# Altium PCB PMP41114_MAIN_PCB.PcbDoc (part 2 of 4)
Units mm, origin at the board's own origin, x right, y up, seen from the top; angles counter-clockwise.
Board outline 159.1 x 70 mm, 6 copper layers (Top Layer, Signal Layer 1, Signal Layer 2, Signal Layer 3, Signal Layer 4, Bottom Layer), stack 1.671 mm thick; 188 components, 146 nets, 720 pads, 326 vias.
Unrouted connection lines stored in the file: 209.
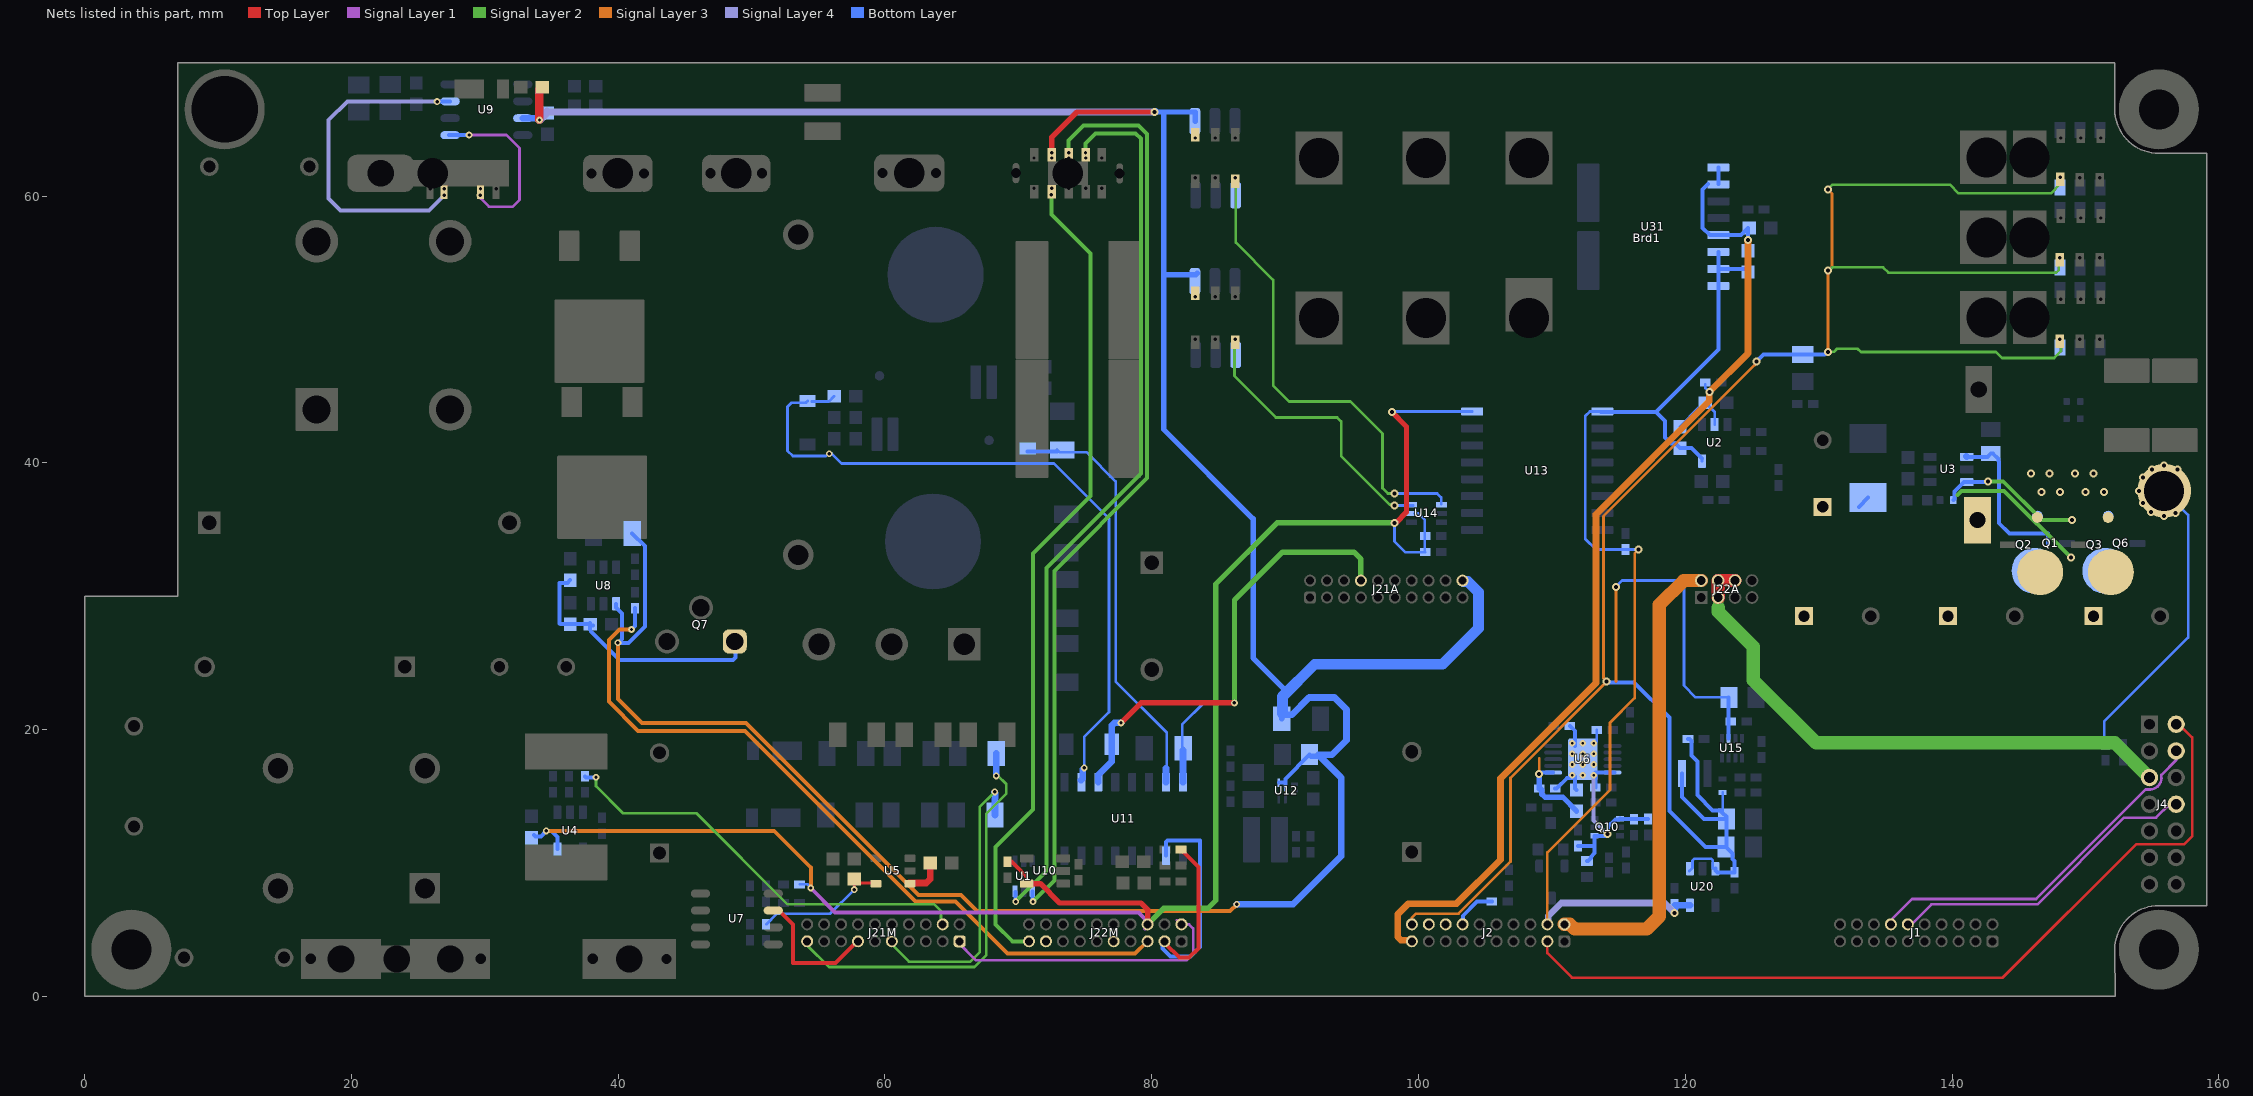
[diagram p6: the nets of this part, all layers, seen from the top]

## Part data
Brd1: library part PMP41114_LLC_MODULE, "3.6kW 400V to 54V FB LLC Module"
C1 C8 C10 C21: library part CMP-0007404-4, "CAP, CERM, 0.1 uF, 25 V, +/- 10%, X7R, 0603", Cap_Case=0603, Manufacturer=MuRata, Supplier Part Number 1=490-1524-1-ND, TempCo=X7R, Tolerance_%=10%, Value1=Unknown, Value2=25V, ValueDisplayed=0.1uF
C2 C3: library part CMP-0091050-1, "TDK 1µF Multilayer Ceramic Capacitor MLCC 500V dc ±20% SMD", Digikey Part Number=495-75234-1-ND, Manufacturer=TDK, Mouser Part Number=871-B58031U5105M062, Operating Temperature Range="-40°C to +150°C", Tolerance_%=20%, ValueDisplayed=1uF
C4 C4A C5 C6: library part CMP-0009877-2, "CAP, AL, 330 uF, 63 V, +/- 20%, 0.045 ohm, TH", Cap_Case=10x25mm, Manufacturer=Chemi-Con, Supplier Part Number 1=565-3965-ND, Tolerance_%=20%, Value1="0.045 ohm", Value2=63V, ValueDisplayed=330uF
C7 C13: library part CMP-0007197-4, "CAP, CERM, 220 pF, 50 V, +/- 5%, C0G/NP0, 0603", Cap_Case=0603, Manufacturer=MuRata, Supplier Part Number 1=490-1435-1-ND, TempCo=C0G/NP0, Tolerance_%=5%, Value1=Unknown, Value2=50V, ValueDisplayed=220pF
C9: library part CMP-0006663-2, "CAP, CERM, 2200 pF, 25 V, +/- 10%, X7R, 0402", Cap_Case=0402, Manufacturer=MuRata, Supplier Part Number 1=490-5419-1-ND, TempCo=X7R, Tolerance_%=10%, Value1=Unknown, Value2=25V, ValueDisplayed=2200pF
C11 C34 C35 C36: library part CMP-0008305-2, "CAP, CERM, 22 uF, 25 V, +/- 20%, X5R, 0805", Cap_Case=0805, Manufacturer=MuRata, Supplier Part Number 1=490-10749-1-ND, TempCo=X5R, Tolerance_%=20%, Value1=Unknown, Value2=25V, ValueDisplayed=22uF
C14: library part CMP-0097294-1, "0.1 µF ±10% 100V Ceramic Capacitor X7R 0603 (1608 Metric)", Digikey Part Number=732-885012206120TR-ND, Manufacturer="Wurth Electronics", Mouser Part Number=710-885012206120, Operating Temperature Range="-55°C to +125°C", TempCo=15%, Temperature Characteristic=X7R, Tolerance_%=10%, ValueDisplayed=100nF
C15 C16 C22: library part CMP-0006563-2, "CAP, CERM, 1 uF, 10 V, +/- 10%, X5R, 0402", Cap_Case=0402, Manufacturer=MuRata, Supplier Part Number 1=490-3890-1-ND, TempCo=X5R, Tolerance_%=10%, Value1=Unknown, Value2=10V, ValueDisplayed=1uF
C17: library part CMP-0007499-4, "CAP, CERM, 2.2 uF, 16 V, +/- 10%, X7R, 0603", Cap_Case=0603, Manufacturer=MuRata, Supplier Part Number 1=81-GRM188Z71C225KE3D, TempCo=X7R, Tolerance_%=10%, Value1=Unknown, Value2=16V, ValueDisplayed=2.2uF
C18: library part CMP-0006641-2, "CAP, CERM, 0.1 uF, 16 V, +/- 10%, X7R, 0402", Cap_Case=0402, Manufacturer=MuRata, Supplier Part Number 1=490-3261-1-ND, TempCo=X7R, Tolerance_%=10%, Value1=Unknown, Value2=16V, ValueDisplayed=0.1uF
C19 C58 C68 C69: library part CMP-0006200-2, "CAP, CERM, 100 pF, 16 V, +/- 10%, X7R, 0402", Cap_Case=0402, Manufacturer=AVX, Supplier Part Number 1=478-7887-1-ND, TempCo=X7R, Tolerance_%=10%, Value1=Unknown, Value2=16V, ValueDisplayed=100pF
C20: library part CMP-0861070-2, "CAP, CERM, 1 µF, 100 V,+/- 10%, X7R, AEC-Q200 Grade 1, 0805", Cap_Case=0805, Manufacturer=AVX, TempCo=X7R, Tolerance_%=10%, Value2=100V, ValueDisplayed=1µF
C23 C27 C28: library part CMP-0006691-2, "CAP, CERM, 470 pF, 50 V, +/- 10%, X7R, 0402", Cap_Case=0402, Manufacturer=MuRata, Supplier Part Number 1=490-1300-1-ND, TempCo=X7R, Tolerance_%=10%, Value1=Unknown, Value2=50V, ValueDisplayed=470pF
C24: library part CMP-0006225-2, "CAP, CERM, 2200 pF, 16 V, +/- 10%, X7R, 0402", Cap_Case=0402, Manufacturer="Wurth Elektronik", TempCo=X7R, Tolerance_%=10%, Value1=Unknown, Value2=16V, ValueDisplayed=2200pF
C25: library part CMP-0120172-1, "10000 pF ±5% 50V Ceramic Capacitor X7R 0603 (1608 Metric)", Digikey Part Number=399-C0603C103J5RAC7867CT-ND, Manufacturer=KEMET, Mouser Part Number=80-C0603C103J5R, Operating Temperature Range="-55°C to +125°C", TempCo=15%, Temperature Characteristic=X7R, Tolerance_%=5%, ValueDisplayed=0.01uF
C26: library part CMP-0080632-1, "CAP, CERM, 1 µF, 10 V,+/- 10%, X7R, 0603", Cap_Case=0603, Manufacturer="Taiyo Yuden", Supplier Part Number 1=587-1242-1-ND, TempCo=X7R, Tolerance_%=10%, Value2=10V, ValueDisplayed=1µF
C29 C30: library part CMP-0006659-2, "CAP, CERM, 0.1 uF, 25 V, +/- 10%, X7R, 0402", Cap_Case=0402, Manufacturer=MuRata, Supplier Part Number 1=490-10698-1-ND, TempCo=X7R, Tolerance_%=10%, Value1=Unknown, Value2=25V, ValueDisplayed=0.1uF
C31 C32 C33 C39 C40: library part CMP-0006752-5, "CAP, CERM, 0.1 uF, 25 V, +/- 5%, X7R, 0603", Cap_Case=0603, Manufacturer=AVX, Supplier Part Number 1=478-3713-1-ND, TempCo=X7R, Tolerance_%=5%, Value1="0.05 ohm", Value2=25V, ValueDisplayed=0.1uF
C41 C42 C48: library part CMP-0009613-2, "CAP, CERM, 2200 pF, 300 V, +/- 20%, E, TH, 2- Leads, Body 9x7mm, Pin Spacing 7.5mm", Cap_Case=9x7x9mm, Manufacturer=MuRata, Supplier Part Number 1=DE6E3KJ222MN3A-ND, TempCo=E, Tolerance_%=20%, Value1=Unknown, Value2=300V, ValueDisplayed=2200pF
C44: library part CMP-0090549-1, "0.47µF Film Capacitor 310V 630V Polypropylene (PP), Metallized Radial", Digikey Part Number=399-12369-ND, Manufacturer=Kemet, Mouser Part Number=80-F862BY474K310ZL, Operating Temperature Range="-40°C to +110°C", Tolerance_%=10%, ValueDisplayed=0.47uF
C45: library part CMP-0093436-1, "1.5 µF Film Capacitor 310V - Polypropylene (PP), Metallized Radial", Digikey Part Number=732-5863-ND, Manufacturer="Wurth Electronics", Mouser Part Number=710-890334026030, Operating Temperature Range="-40°C to +105°C", Tolerance_%=10%, ValueDisplayed=1.5uF
C52 C53: library part CMP-0009248-2, "CAP, CERM, 0.022 uF, 630 V, +/- 10%, X7R, 1210", Cap_Case=1210, Manufacturer=MuRata, Supplier Part Number 1=490-3514-1-ND, TempCo=X7R, Tolerance_%=10%, Value1=Unknown, Value2=630V, ValueDisplayed=0.022uF
C54: library part CMP-0064947-2, "CAP, CERM, 1 uF, 6.3 V,+/- 10%, X7R, 0402", Cap_Case=0402, Manufacturer=MuRata, Supplier Part Number 1=490-10024-1-ND, TempCo=X7R, Tolerance_%=10%, Value1=Unknown, Value2=6.3V, ValueDisplayed=1uF
C55 C62 C63 C981 C982: library part CMP-0006623-2, "CAP, CERM, 0.1 uF, 6.3 V, +/- 10%, X7R, 0402", Cap_Case=0402, Manufacturer=MuRata, Supplier Part Number 1=GRM155R70J104KA01D-ND, TempCo=X7R, Tolerance_%=10%, Value1=Unknown, Value2=6.3V, ValueDisplayed=0.1uF
C56: library part CMP-0006529-2, "CAP, CERM, 1000 pF, 6.3 V, +/- 10%, X5R, 0402", Cap_Case=0402, Manufacturer=MuRata, Supplier Part Number 1=GRM155R60J102KA01D-ND, TempCo=X5R, Tolerance_%=10%, Value1=Unknown, Value2=6.3V, ValueDisplayed=1000pF
C57 C59: library part CMP-0007678-2, "CAP, CERM, 10 uF, 16 V, +/- 20%, X5R, 0805", Cap_Case=0805, Manufacturer=AVX, Supplier Part Number 1=1582704, TempCo=X5R, Tolerance_%=20%, Value1=Unknown, Value2=16V, ValueDisplayed=10uF
C60 C74: library part CMP-0008691-2, "CAP, CERM, 1 uF, 25 V, +/- 10%, X7R, 1206", Cap_Case=1206, Manufacturer=TDK, Supplier Part Number 1=445-1592-1-ND, TempCo=X7R, Tolerance_%=10%, Value1="0.01 ohm", Value2=25V, ValueDisplayed=1uF
C61: library part CMP-0007040-4, "CAP, CERM, 1 uF, 25 V, +/- 10%, X7R, 0603", Cap_Case=0603, Manufacturer=TDK, Supplier Part Number 1=445-5956-1-ND, TempCo=X7R, Tolerance_%=10%, Value1=Unknown, Value2=25V, ValueDisplayed=1uF
C64 C65: library part CMP-0006764-4, "CAP, CERM, 1000 pF, 50 V, +/- 10%, C0G/NP0, 0603", Cap_Case=0603, Manufacturer=AVX, Supplier Part Number 1=478-3718-1-ND, TempCo=C0G/NP0, Tolerance_%=10%, Value1="0.048 ohm", Value2=50V, ValueDisplayed=1000pF
C66: library part CMP-0006978-4, "CAP, CERM, 0.01 uF, 50 V, +/- 10%, X7R, 0603", Cap_Case=0603, Manufacturer=Kemet, Supplier Part Number 1=399-5346-1-ND, TempCo=X7R, Tolerance_%=10%, Value1=Unknown, Value2=50V, ValueDisplayed=0.01uF
C67: library part CMP-0008641-2, "CAP, CERM, 0.1 uF, 25 V, +/- 5%, C0G/NP0, 1206_190", Cap_Case=1206, Manufacturer=Kemet, Supplier Part Number 1=399-5750-1-ND, TempCo=C0G/NP0, Tolerance_%=5%, Value1=Unknown, Value2=25V, ValueDisplayed=0.1uF
C70: library part CMP-0008689-2, "CAP, CERM, 10 uF, 10 V, +/- 20%, X7R, 1206", Cap_Case=1206, Manufacturer=TDK, Supplier Part Number 1=445-1602-1-ND, TempCo=X7R, Tolerance_%=20%, Value1="0.0046 ohm", Value2=10V, ValueDisplayed=10uF
C71: library part CMP-0007728-2, "CAP, CERM, 1 uF, 25 V, +/- 10%, X7R, 0805", Cap_Case=0805, Manufacturer=Kemet, Supplier Part Number 1=399-8004-1-ND, TempCo=X7R, Tolerance_%=10%, Value1=Unknown, Value2=25V, ValueDisplayed=1uF
C73: library part CMP-0007989-2, "CAP, CERM, 22 uF, 6.3 V, +/- 10%, X5R, 0805", Cap_Case=0805, Manufacturer="Samsung Electro-Mechanics", TempCo=X5R, Tolerance_%=10%, Value1=Unknown, Value2=6.3V, ValueDisplayed=22uF
C75: library part CMP-0007402-5, "CAP, CERM, 1000 pF, 25 V, +/- 10%, X7R, 0603", Cap_Case=0603, Manufacturer=MuRata, Supplier Part Number 1=GRM188R71E102KA01D-ND, TempCo=X7R, Tolerance_%=10%, Value1=Unknown, Value2=25V, ValueDisplayed=1000pF
C76: library part CMP-0006201-2, "CAP, CERM, 0.1 uF, 16 V, +/- 10%, X7R, 0402", Cap_Case=0402, Manufacturer=AVX, Supplier Part Number 1=478-7888-1-ND, TempCo=X7R, Tolerance_%=10%, Value1=Unknown, Value2=16V, ValueDisplayed=0.1uF
C114 C120 C123 C130: library part CMP-0098127-1, "180 µF 450 V Aluminum Electrolytic Capacitors Radial, Can 3000 Hrs @ 105°C", Digikey Part Number=1189-450HXW180MEFR16X50-ND, Leakage Current=853.8uA, Manufacturer=Rubycon, Mouser Part Number=232-450HXW180MEFR16X, Operating Temperature Range="-40°C to +105°C", Tolerance_%=20%, ValueDisplayed=180uF
C215: library part CMP-0006708-2, "CAP, CERM, 3300 pF, 100 V, +/- 10%, X7R, 0402", Cap_Case=0402, Manufacturer=MuRata, Supplier Part Number 1=GRM155R72A332KA01D-ND, TempCo=X7R, Tolerance_%=10%, Value1=Unknown, Value2=100V, ValueDisplayed=3300pF
D1 D2: library part CMP-0086603-1, "DIODE GEN PURPOSE 600V SLIMDPAK", Manufacturer=Vishay
D3: library part CMP-0028394-2, "Diode, Schottky, 80 V, 1 A, SMB", Manufacturer="Diodes Inc.", Value1=1A, Value2=0.79V
D4: library part CMP-0076979-3, "Diode, Switching, 100 V, 0.25 A, SOD-523", Manufacturer=Nexperia, Value1=0.25A, Value2=1.25V
D8 D10: library part CMP-0028548-2, "Diode, Schottky, 40 V, 1 A, SOD-123FL", Manufacturer="ON Semiconductor", Value1=1A, Value2=0.55V
D9 D12 D15: library part CMP-0076978-2, "Diode, Standard Recovery Rectifier, 600 V, 1 A, PowerDI123", Manufacturer="Diodes Inc.", Value1=1A, Value2=1.1V
D11: library part CMP-0090872-1, "Diode Array 1 Pair Common Cathode Standard 600V 30A Through Hole TO-3P-3, SC-65-3", Digikey Part Number=FFA60UA60DN-ND, Forward Current=30A, Manufacturer="ON Semiconductor", Max Surge Forward Current=180A, Mouser Part Number=512-FFA60UA60DN, Operating Temperature Range="-65°C to +175°C", Peak Reverse Current=100uA
J1 J2 J21A J21M J22M: library part CMP-0750171-1, "Receptacle, 1.27mm, 10x2, Gold, TH", Color=Black, Current_A=1A, Manufacturer="Sullins Connector Solutions"
J4: library part CMP-0089162-1, "Connector Header Through Hole 14 position 0.079\" (2.00mm)", Current_A=2A, Digikey Part Number=3M9188-14-ND, Manufacturer=3M, Mouser Part Number=517-951214-8622-AR, Operating Temperature Range="-55°C to +125°C"
J5: library part CMP-0122913-1, "Power Entry Connector Receptacle, Male Blades IEC 320-C20 Panel Mount, Snap-In", Current_A=20A, Digikey Part Number=486-3988-ND, Manufacturer=Schurter, Mouser Part Number=693-4793.8000, Operating Temperature Range="-25°C to +70°C", Voltage_V=250V
J22A: library part CMP-0065025-2, "Header, 1.27mm, 4x2, Gold, TH", Color=Black, Current_A=1A, Manufacturer=FCI, Supplier Part Number 1=609-3711-ND, Voltage_V=125V
L1: library part CMP-0091020-1, "Inductor Buck/Boost, Toroid, TH, 100uH 15% 8A", Manufacturer="Pulse Electronics", Operating Temperature Range="-40°C to +125°C", Test Frequency=100kHz, Tolerance_%=15%
L2: library part CMP-0091106-1, "IND, CUR-SENSE, 4MH, 20A, TOR, TH", Manufacturer="Pulse Electronics", Operating Temperature Range="-40°C to +125°C", Voltage_Isolation_Vrms=1500VDC
L3: library part CMP-0091125-1, "INDUCTOR CUR-SENSE 8.3mH TOR TH", Manufacturer="Pulse Electronics", Operating Temperature Range="-40°C to +125°C", Test Frequency=10kHz, Tolerance_%=30%
L4: library part CMP-0091118-1, "Inductor Power 300uH", Manufacturer="Pulse Electronics", Operating Temperature Range="-40°C to +125°C", Test Frequency=100kHz, Tolerance_%=15%
L5: library part CMP-0087867-1, "2.2µH Shielded Molded Inductor 2.4A 67mOhm Max 2-SMD", Manufacturer="Wurth Electronics"
L6: library part CMP-0063086-1, "Inductor, Wirewound, Ferrite, 10 uH, 0.68 A, 0.46 ohm, SMD", Manufacturer="Würth Elektronik", Value1="0.843 ohm", Value2=0.6A, ValueDisplayed=10uH
Logo1: library part CMP-0074769-1
Q1 Q2 Q3 Q6: library part CMP-0122332-1, "N-Channel 80 V 31A (Ta), 323A (Tc) 3W (Ta), 333W (Tc) Surface Mount PG-TTFN-9-U02", Digikey Part Number=448-IQD016N08NM5CGATMA1CT-ND, Drain To Source Breakdown Voltage=80V, Input Capacitace At Vds="7100pF @ 40V", Manufacturer=Infineon, Mouser Part Number=726-IQD016N08NM5CGAT, Operating Temperature Range="-55°C to +175°C", Power_W=3W, Pulse Drain Current=1292A, Typ Forward Diode Voltage=0.82V
Q4 Q5: library part CMP-0086487-1, "N-Channel 600V 23A (Tc) 390W (Tc) Surface Mount PG-HSOF-8-2", Manufacturer=Infineon
Q7: library part CMP-0001223-3, "MOSFET N-CH 600V 48A TO220-3", Alternate Manufacturer=None, Manufacturer="Infineon Technologies"
Q8: library part CMP-0097439-1, "Bipolar (BJT) Transistor PNP 60 V 600 mA 200MHz 300 mW Surface Mount SOT-23-3 (TO-236)", Collector Base Voltage=-60V, Digikey Part Number=SMMBT2907ALT3GOSCT-ND, Emitter Base Voltage=-5V, Manufacturer="On Semiconductor", Mouser Part Number=863-SMMBT2907ALT3G, Operating Temperature Range="-55°C to +150°C", Power_W=225mW, Unity Gain Freq=200MHz
Q9: library part CMP-0083635-2, "MOSFET, P-CH, -60 V, -0.18 A, SOT-23", Alternate Manufacturer=None, Manufacturer="Fairchild Semiconductor", Value1="7.5 ohm", Value2="1.8 nC"
Q10: library part CMP-0000770-1, "MOSFET, 2-CH, N-CH, 60 V, 0.115 A, SOT-363", Alternate Manufacturer=None, Manufacturer="Fairchild Semiconductor", Supplier Part Number 1=2N7002DWCT-ND
R1 R9: library part CMP-0025983-3, "RES, 120 k, 1%, 0.063 W, AEC-Q200 Grade 0, 0402", Manufacturer=Vishay-Dale, Power_W=63mW, Supplier Part Number 1=541-120KLCT-ND, TempCo="100 ppm/C", Tolerance_%=1%, Value2=0.063W, Value_Code=120k
R2 R3 R4 R5: library part CMP-0095938-1, "500 µOhms ±1% 6W Chip Resistor 2512 (6432 Metric) Automotive AEC-Q200, Current Sense Metal Element", Digikey Part Number=CSS2H-2512R-L500FCT-ND, Manufacturer=Bourns, Mouser Part Number=652-CSS2H2512RL500F, Operating Temperature Range="-55°C to +170°C", Power_W=6W, TempCo=100ppm/°C, Tolerance_%=1%
R6 R8 R10 R17: library part CMP-0026716-1, "RES, 1.00 k, 1%, 0.063 W, 0402", Manufacturer=Rohm, Power_W=63mW, Supplier Part Number 1=RHM1.00KLCT-ND, TempCo="100 ppm/C", Tolerance_%=1%, Value2=0.063W, Value_Code=1k00, ValueDisplayed=1.00k
R7: library part CMP-0026951-5, "RES, 5.1 k, 5%, 0.063 W, AEC-Q200 Grade 0, 0402", Manufacturer=Vishay-Dale, Power_W=63mW, Supplier Part Number 1=541-5.1KJCT-ND, TempCo="200 ppm/C", Tolerance_%=5%, Value2=0.063W, Value_Code=5k10, ValueDisplayed=5.1k
R11: library part CMP-0094733-1, "100Ω ±1% 0.063W 0402 Thick Film Chip Resistor AEC-Q200 compliant", Manufacturer="Stackpole Electronics", Operating Temperature Range="-55°C to +155°C", Power_W=63mW, TempCo=100ppm/°C, Tolerance_%=1%
R12: library part CMP-0026684-1, "RES, 240, 1%, 0.1 W, AEC-Q200 Grade 0, 0402", Manufacturer=Panasonic, Power_W=100mW, Supplier Part Number 1=P240LCT-ND, TempCo="100 ppm/C", Tolerance_%=1%, Value2=0.1W, Value_Code=240R, ValueDisplayed=240
R13: library part CMP-0026030-3, "RES, 15.0, 1%, 0.063 W, AEC-Q200 Grade 0, 0402", Manufacturer=Vishay-Dale, Power_W=63mW, Supplier Part Number 1=541-15.0LCT-ND, TempCo="100 ppm/C", Tolerance_%=1%, Value2=0.063W, Value_Code=15R0, ValueDisplayed=15.0
R14: library part CMP-0078244-2, "RES, 30.0 k, 1%, 0.063 W, AEC-Q200 Grade 0, 0402", Manufacturer=Vishay-Dale, Power_W=63mW, Supplier Part Number 1=541-30.0KLCT-ND, TempCo="100 ppm/C", Tolerance_%=1%, Value2=0.063W, Value_Code=30k0, ValueDisplayed=30.0k
R15 R18 R19: library part CMP-0026722-1, "RES, 100, 1%, 0.063 W, 0402", Manufacturer="Yageo America", Power_W=63mW, Supplier Part Number 1=311-100LRCT-ND, TempCo="100 ppm/C", Tolerance_%=1%, Value2=0.063W, Value_Code=100R, ValueDisplayed=100
R16: library part CMP-0078583-1, "RES, 15.0 k, 1%, 0.063 W, 0402", Manufacturer="Yageo America", Power_W=63mW, Supplier Part Number 1=311-15.0KLRCT-ND, TempCo="100 ppm/C", Tolerance_%=1%, Value2=0.063W, Value_Code=15k0, ValueDisplayed=15.0k
R20 R23: library part CMP-0026658-1, "RES, 10.0 k, 1%, 0.1 W, 0402", Manufacturer=Panasonic, Power_W=100mW, Supplier Part Number 1=P10.0KLCT-ND, TempCo="100 ppm/C", Tolerance_%=1%, Value2=0.1W, Value_Code=10k0, ValueDisplayed=10.0k
R21 R24 R82 R86: library part CMP-0027004-2, "RES, 0, 5%, 0.063 W, 0402", Manufacturer="Yageo America", Power_W=63mW, Supplier Part Number 1=311-0.0JRCT-ND, TempCo="200 ppm/C", Tolerance_%=5%, Value2=0.063W, Value_Code=0000, ValueDisplayed=0
R22: library part CMP-0077552-1, "RES, 45.3 k, 1%, 0.063 W, 0402", Manufacturer="Yageo America", Power_W=63mW, Supplier Part Number 1=311-45.3KLRCT-ND, TempCo="100 ppm/C", Tolerance_%=1%, Value2=0.063W, Value_Code=45k3, ValueDisplayed=45.3k
R42 R45: library part CMP-0026549-2, "RES, 787 k, 1%, 0.063 W, AEC-Q200 Grade 0, 0402", Manufacturer=Vishay-Dale, Power_W=63mW, Supplier Part Number 1=541-787KLCT-ND, TempCo="100 ppm/C", Tolerance_%=1%, Value2=0.063W, Value_Code=787k
R43 R46: library part CMP-0026555-2, "RES, 7.50 k, 1%, 0.063 W, AEC-Q200 Grade 0, 0402", Manufacturer=Vishay-Dale, Power_W=63mW, Supplier Part Number 1=541-7.50KLCT-ND, TempCo="100 ppm/C", Tolerance_%=1%, Value2=0.063W, Value_Code=7k50, ValueDisplayed=7.50k
R47 R48 R49 R50 R51 R52 R60 R61 R62 R84 R85 R87: library part CMP-0018215-2, "RES, 348 k, 1%, 0.25 W, 1206", Manufacturer="Yageo America", Power_W=250mW, Supplier Part Number 1=311-348KFRCT-ND, TempCo="100 ppm/C", Tolerance_%=1%, Value2=0.25W, Value_Code=348k
R57 R65 R77: library part CMP-0021998-4, "RES, 10.0 k, 1%, 0.1 W, AEC-Q200 Grade 0, 0603", Manufacturer=Vishay-Dale, Power_W=100mW, Supplier Part Number 1=541-10.0KHCT-ND, TempCo="100 ppm/C", Tolerance_%=1%, Value2=0.1W, Value_Code=10k0, ValueDisplayed=10.0k
R58: library part CMP-0022523-4, "RES, 5.11, 1%, 0.1 W, AEC-Q200 Grade 0, 0603", Manufacturer=Vishay-Dale, Power_W=100mW, Supplier Part Number 1=541-5.11HHCT-ND, TempCo="100 ppm/C", Tolerance_%=1%, Value2=0.1W, Value_Code=5R11, ValueDisplayed=5.11
R64: library part CMP-0017283-3, "RES, 1.00 k, 1%, 0.25 W, AEC-Q200 Grade 0, 1206", Manufacturer=Panasonic, Power_W=250mW, Supplier Part Number 1=P1.00KFCT-ND, TempCo="100 ppm/C", Tolerance_%=1%, Value2=0.25W, Value_Code=1k00, ValueDisplayed=1.00k
R83: library part CMP-0027004-2, Manufacturer="Yageo America", Power_W=63mW, Supplier Part Number 1=311-0.0JRCT-ND, TempCo="200 ppm/C", Tolerance_%=5%, Value2=0.063W, Value_Code=0000, ValueDisplayed=0
R88: library part CMP-0026822-3, "RES, 0, 5%, 0.063 W, AEC-Q200 Grade 0, 0402", Manufacturer=Vishay-Dale, Power_W=63mW, Supplier Part Number 1=541-0.0JCT-ND, TempCo="200 ppm/C", Tolerance_%=5%, Value2=0.063W, Value_Code=0000, ValueDisplayed=0
R89: library part CMP-0022201-5, "RES, 200, 1%, 0.1 W, AEC-Q200 Grade 0, 0603", Manufacturer=Vishay-Dale, Power_W=100mW, Supplier Part Number 1=541-200HCT-ND, TempCo="100 ppm/C", Tolerance_%=1%, Value2=0.1W, Value_Code=200R, ValueDisplayed=200
R90: library part CMP-0025704-4, "RES, 10, 5%, 0.25 W, AEC-Q200 Grade 0, 0603", Manufacturer=Vishay-Dale, Power_W=250mW, Supplier Part Number 1=541-10SACT-ND, TempCo="200 ppm/C", Tolerance_%=5%, Value2=0.25W, Value_Code=10R0, ValueDisplayed=10
R91 R98: library part CMP-0025697-4, "RES, 0, 5%, 0.1 W, AEC-Q200 Grade 0, 0603", Manufacturer=Vishay-Dale, Power_W=100mW, Supplier Part Number 1=541-0.0GCT-ND, TempCo="200 ppm/C", Tolerance_%=5%, Value2=0.1W, Value_Code=0000, ValueDisplayed=0
R150: library part CMP-0092403-1, "RES 0.0025 OHM 1% 5W 3921", Manufacturer=Vishay, Mouser Part Number=71-WSLP3921L1000FEA, Operating Temperature Range="-65°C to +170°C", Power_W=5W, TempCo=350ppm/°C, Tolerance_%=1%
R248: library part CMP-0026547-2, "RES, 76.8 k, 1%, 0.063 W, AEC-Q200 Grade 0, 0402", Manufacturer=Vishay-Dale, Power_W=63mW, Supplier Part Number 1=541-76.8KLCT-ND, TempCo="100 ppm/C", Tolerance_%=1%, Value2=0.063W, Value_Code=76k8, ValueDisplayed=76.8k
R249: library part CMP-0022014-4, "RES, 118 k, 1%, 0.1 W, AEC-Q200 Grade 0, 0603", Manufacturer=Vishay-Dale, Power_W=100mW, Supplier Part Number 1=541-118KHCT-ND, TempCo="100 ppm/C", Tolerance_%=1%, Value2=0.1W, Value_Code=118k
R251 R271: library part CMP-0026721-1, "RES, 100 k, 1%, 0.0625 W, 0402", Manufacturer="Yageo America", Power_W=62.5mW, Supplier Part Number 1=311-100KLRCT-ND, TempCo="100 ppm/C", Tolerance_%=1%, Value2=0.0625W, Value_Code=100k
RJ01 RJ02: library part CMP-0002710-1, "0 Ohms Jumper Chip Resistor 0402 (1005 Metric) Automotive AEC-Q200 Thick Film", Digikey Part Number=P0.0JCT-ND, Manufacturer=Panasonic, Mouser Part Number=667-ERJ-2GE0R00X, Operating Temperature Range="-55°C to +155°C", Power=100mW
RT2: library part CMP-0002562-2, "Thermistor NTC, 50 ohm, 25%, D12.5xH16.5mm", Manufacturer=TDK, Supplier Part Number 1=495-3880-ND, Tolerance_%=25%
U1: library part CMP-0051787-3, "Dual Buffer/Driver with Open-Drain Output, DCK0006A (SOT-SC70-6)", Alternate Manufacturer="Texas Instruments", Alternate PartNumber=SN74LVC2G07DCKR, F @ Nom Voltage(Max)(Mhz)=150, Generic Part Number=SN74LVC2G07, ICC @ Nom Voltage(Max)(mA)=0.01, Operating Temperature Range(C)="-40 to 125", Rating=Catalog, tpd @ Nom Voltage(Max)(ns)=8.6,4.4,3.7,2.9, Voltage(Nom)(V)=1.8,2.5,3.3,5
U2: library part CMP-0073542-1, "TLVx376, 5.5 MHz, Low-Noise, Low Quiescent Current, Precision Operational Amplifiers, DBV0005A (SOT-23-5)", Alternate Manufacturer="Texas Instruments", Alternate PartNumber=TLV376IDBVT
U3: library part CMP-0066129-2, "High Side OR-ing FET Controller, DDC0006A (SOT-23-T-6)", Alternate Manufacturer="Texas Instruments"
U4: library part CMP-0068676-2, "88 MHz, Precision, Low Noise, 1.8V CMOS Input, Decompensated Operational Amplifier, DBV0005A (SOT-23-5)", Manufacturer="Texas Instruments", Operating Temperature Range="-40 to 125 C", Rating=Catalog
U5: library part CMP-0076429-1, "8 ppm/degC Drift, Low-Power, Dual-Output Vref and Vref/2 Voltage Reference, DDC0005A (SOT-23-T-5)", Alternate Manufacturer="Texas Instruments", Alternate PartNumber=REF2025AIDDCT
U6: library part CMP-0074287-2, "Precision Voltage-to-Current Converter/Transmitter, DGQ0010D (VSSOP-10)", Alternate Manufacturer="Texas Instruments"
U7: library part CMP-0081537-2, "TMCS1100A1DT, D0008A (SOIC-8)", Alternate Manufacturer="Texas Instruments"
U8: library part CMP-0066946-1, "4A/8A Single Channel High-speed Low-side Gate Driver, DBV0006A (SOT-23-6)", Alternate Manufacturer="Texas Instruments", Alternate PartNumber=UCC27511DBVT
U9: library part CMP-0013005-2, "620-V High-Side Low-Side Gate Driver with 2.5A Peak Output and RobustDrive, D0008A (SOIC-8)", Alternate Manufacturer="Texas Instruments", Alternate PartNumber=UCC27712D
U10 U20: library part CMP-0066771-1, "150-mA, Low-Dropout Regulator with Foldback Current Limit for Portable Devices, DBV0005A (SOT-23-5)", Alternate Manufacturer="Texas Instruments", Alternate PartNumber=TLV71333PDBVT
U11: library part CMP-0077646-2, "4-A, 6-A, 3.0-kVRMS Isolated Dual-Channel Gate Driver, D0016B (SOIC-16)", Alternate Manufacturer="Texas Instruments", Alternate PartNumber=UCC21220D, Operating Temperature Range="-40 to 125 C", Rating=Catalog
U12: library part CMP-0084864-4, "2.9-V to 18-V, 4-A Synchronous Buck Converters, RPJ0009A (VQFN-HR-9)", Alternate Manufacturer="Texas Instruments", Alternate PartNumber=TPS62901RPJT
U13: library part CMP-0092396-1, "General Purpose Digital Isolator 5000Vrms 6 Channel 100Mbps 85kV/µs CMTI 16-SOIC (0.295\", 7.50mm Width)", Digikey Part Number=296-ISO7762FDWRCT-ND, Manufacturer="Texas Instruments", Max Supply Voltage=5.5V, Min Supply Voltage=2.25V, Mouser Part Number=595-ISO7762FDWR, Nominal Supply Current=2.1-25.7mA, Operating Temperature Range="-55°C to +125°C"
U14: library part CMP-0051004-3, "Single 3-Input Positive OR-AND Gate, DCK0006A (SOT-SC70-6)", F @ Nom Voltage(Max)(Mhz)=150, Generic Part Number=SN74LVC1G3208, ICC @ Nom Voltage(Max)(mA)=0.01, Manufacturer="Texas Instruments", Operating Temperature Range="-40 to 125,-40 to 85 C", Rating=Catalog, tpd @ Nom Voltage(Max)(ns)=17.5,7.5,5.9,4.5, Voltage(Nom)(V)=1.8,2.5,3.3,5
U15: library part CMP-0861057-2, "4.2-V to 17-V Input, 2-A Synchronous Buck Converter, DRL0008A (SOT-5X3-8)", Alternate Manufacturer="Texas Instruments"
U31: library part CMP-0097985-1, Manufacturer="Texas Instruments", Operating Temperature Range=to, Part Number=TMCS1133B2QDVGR

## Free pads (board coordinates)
  round 6 hole 3: 1(3.5,3.5) 1(155.5,3.5)
  round 6 hole 5: 1(10.5,66.5)
  oval 1.27x2.794 hole 0.762 slot 2.286 at 90 deg: 1(16.948,2.821) 1(29.698,2.821) 1(37.998,61.696) 1(38.098,2.821) 1(41.948,61.696) 1(43.623,2.796) 1(46.925,61.7) 1(50.775,61.7) 1(59.825,61.725) 1(63.825,61.725)
  rrect50% 5x2.8 hole 2: 1(22.196,61.696)
  rect 11.43x2 hole 2 square unplated: 1(23.405,2.801)
  rect 0.508x1.016 hole 0.254 copper offset 0,-0.254: 1(25.9,60.55) 1(26.95,60.55) 1(29.675,60.55) 1(30.85,60.55)
  rect 11.43x2 hole 2.286 square unplated: 1(26.109,61.696)
  oval 5x1.27 hole 0.8 slot 4 at 0 deg: 1(39.875,60.95) 1(40.025,62.425) 1(48.9,60.95) 1(48.9,62.425)
  rect 4x1.3 hole 2.286 square unplated: 1(39.975,61.7) 1(48.85,61.7) 1(61.825,61.725)
  oval 5.08x1.27 hole 0.762 slot 4.572 at 0 deg: 1(61.775,60.975) 1(61.775,62.475)
  oval 0.508x1.524 hole 0.762 slot 2.286 at 90 deg unplated: 1(69.821,61.718) 1(77.596,61.693)
  rect 0.635x1.016 hole 0.254 copper offset 0,-0.254: 1(71.175,60.575) 1(72.5,60.575) 1(73.775,60.575) 1(75.05,60.575) 1(76.25,60.575) 1(83.275,49.275) 1(83.275,61.375) 1(84.775,49.275) 1(84.775,61.375) 1(86.275,49.275) 1(86.275,61.375)
  rect 0.635x1.016 hole 0.254 copper offset 0,0.254: 1(71.175,62.85) 1(72.5,62.85) 1(73.775,62.85) 1(75.05,62.85) 1(76.25,62.85) 1(83.25,52.45) 1(83.25,64.35) 1(84.75,52.45) 1(84.75,64.35) 1(86.25,52.45) 1(86.25,64.35)
  rect 3x1.778 hole 2.286 square unplated: 1(73.705,61.715)
  rect 2x3.5 hole 1.2 square: 1(141.9,35.7) 1(142,45.5)
  rect 0.635x1.016 / inner rrect50% 0.635x0.4 / far side rect 0.635x1.016 hole 0.254 copper offset 0,-0.15: 1(148.075,49.275) 1(148.075,55.375) 1(148.1,61.4) 1(149.575,49.275) 1(149.575,55.375) 1(149.575,61.375) 1(151.075,49.275) 1(151.075,55.375) 1(151.075,61.375)
  rect 0.635x1.016 / inner rrect50% 0.635x0.4 / far side rect 0.635x1.016 hole 0.254 copper offset 0,0.15: 1(148.15,52.25) 1(148.15,58.35) 1(148.15,64.35) 1(149.65,52.25) 1(149.65,58.35) 1(149.65,64.35) 1(151.15,52.25) 1(151.15,58.35) 1(151.15,64.35)
  round 6 / inner round 4 / far side round 6 hole 3: 1(155.5,66.5)
  rect 7x3 hole 2 square: 2(40.836,2.801)
  rect 6x3 hole 2 square: 3(27.405,2.801) 4(19.22,2.801)

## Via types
v1: diameter 0.6, hole 0.3, Top Layer to Bottom Layer, tented both sides, 153 vias
v2: diameter 0.508, hole 0.254, Top Layer to Bottom Layer, tented both sides, 73 vias
v3: diameter 1.27, hole 0.711, Top Layer to Bottom Layer, tented both sides, 70 vias
v4: diameter 0.5, hole 0.2, Top Layer to Bottom Layer, tented both sides, 12 vias
v5: diameter 1.1, hole 0.711, Top Layer to Bottom Layer, tented both sides, 8 vias
v6: diameter 0.5, hole 0.2, Top Layer to Bottom Layer, 6 vias
v7: diameter 1.4, hole 0.9, Top Layer to Bottom Layer, tented both sides, 2 vias
v8: diameter 4, hole 3, Top Layer to Bottom Layer, tented both sides, 1 vias
v9: diameter 4/3/4/4/4/4 (per signal layer), hole 3, Top Layer to Bottom Layer, tented both sides, 1 vias

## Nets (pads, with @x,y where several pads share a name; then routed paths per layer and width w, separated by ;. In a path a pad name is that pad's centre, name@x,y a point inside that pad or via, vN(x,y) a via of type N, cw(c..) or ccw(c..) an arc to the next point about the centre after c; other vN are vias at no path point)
1V25: C33.2 U5.1 | length 2.9
  Top Layer w0.5: U5.1@61.8,8.5 63.1,8.5 63.4,8.8 C33.2@63.4,10
1V65_ref: J21M.4 R45.1 | length 32.3
  Signal Layer 2 w0.2: v2(38.338,16.424) 38.338,15.762 40.373,13.727 45.873,13.727 52.7,6.9 63.7,6.9 64.2,6.4 64.2,5.6 J21M.4@64.4,5.4
  Bottom Layer w0.3: R45.1@37.5,16.5 37.6,16.4 v2@38.3,16.4
2V5ref: C32.2 R86.2 U5.5 | length 9.9
  Top Layer w0.2: v2(57.7,8) C32.2@57.7,8.6 ; C32.2@57.8,8.7 58,8.5 U5.5@59.3,8.5
  Bottom Layer w0.2: R86.2@51.1,5.4 51.9,6.2 55.9,6.2 v2(57.7,8)
3.3Vc-s: C8.2 C10.1 C16.1 C982.1 J2.4 U2.5 U13.1 U20.5 U31.8 U31.9 U31.10 | length 84.7
  Signal Layer 3 w0.2: J2.4@109.66,5.4 109.66,10.79 114.35,15.48 114.35,20.512 116.2,22.362 116.2,33.183 116.5,33.483 v1(116.5,33.5)
  Signal Layer 4 w0.5: J2.4@109.66,5.4 109.729,5.469 109.729,6.029 110.7,7 118.449,7 v1(119.2,6.249)
  Bottom Layer w0.2: U13.1@113.775,43.845 112.845,43.845 112.5,43.5 112.5,34.3 113.3,33.5 C16.1@115.5,33.5 v1(116.5,33.5) ; U2.5@121.25,40.125 U2.5@121.25,40.325
  Bottom Layer w0.3: J2.4@109.66,5.4 J2.4@109.775,5.515 ; U13.1@113.689,43.8 117.8,43.8 ; U2.5@121.25,40.325 120.475,41.1 C8.2@119.6,41.1 119.6,41.106 119.275,41.431 118.919,41.431 118.462,41.888 118.462,43.138 117.8,43.8 ; U31.8@122.475,55.795 U31.9@122.475,54.525 U31.9@122.5,54.525 ; 122.5,53.8 122.5,48.5 117.8,43.8 ; 122.5,53.9 U31.9@122.5,54.525 ; C10.1@124.7,54.4 124.575,54.525 U31.9@122.5,54.525
  Bottom Layer w0.5: v1(119.2,6.249) 119.2,6.824 U20.5@120.35,6.824
3V3: C15.1 C22.1 C26.1 C62.1 J22M.6 R83.2 U4.5 U10.5 U13.16 U14.5 | length 134.1
  Top Layer w0.2: v1(98,43.8) v1@98,43.9
  Top Layer w0.3: C62.1@69.2,10.1 69.5,10.1 70.6,9 U10.5@70.6,8.5
  Top Layer w0.4: U10.5@70.625,8.45 71.65,8.45 73.1,7 79.2,7 79.69,6.51 J22M.6@79.69,5.4 ; v1(98,43.8) 99.1,42.7 99.1,36.3 v1@98.3,35.5
  Signal Layer 1 w0.3: v2(54.438,8.124) 56.262,6.3 79,6.3 79.5,5.8 J22M.6@79.5,5.1
  Signal Layer 2 w0.4: J22M.6@79.69,5.4 80.89,6.6 84.2,6.6 84.8,7.2 84.8,30.9 89.4,35.5 v1(98.2,35.5)
  Signal Layer 3 w0.3: v2(34.6,12.4) 51.7,12.4 54.438,9.662 v2(54.438,8.124)
  Bottom Layer w0.2: R83.2@53.6,8.4 54.2,8.4 v2@54.4,8.2 ; v1(98,43.8) 98.045,43.845 U13.16@104.025,43.845 ; v1(98.2,35.5) 98.2,34.1 99,33.3 C22.1@100.5,33.3 100.473,33.327 100.473,35.727 100,36.2 U14.5@99.7,36.2
  Bottom Layer w0.3: C26.1@33.7,12.1 33.8,12 34.2,12 v2(34.6,12.4) 35,12.4 35.45,11.95 U4.5@35.45,11.05 ; v2@54.413,8.1 v2(54.438,8.124)
5Vc-s: Brd1.S5 C11.1 C35.1 C36.1 C981.1 J2.20 L6.2 pad.1@148.1,61.4 pad.1@148.075,49.275 pad.1@148.075,55.375 R20.2 R22.1 U20.1 U20.3 | length 169.7
  Signal Layer 2 w0.2: v1(130.7,48.3) 130.713,48.313 131.135,48.313 131.372,48.55 132.923,48.55 133.173,48.3 143.293,48.3 143.743,47.85 147.65,47.85 148.164,48.364 148.164,48.8 ; v1@130.713,54.413 130.78,54.413 131.017,54.65 134.818,54.65 135.218,54.25 147.805,54.25 147.986,54.432 pad.1@147.986,55.086 ; v1@130.713,60.513 131.05,60.85 139.84,60.85 140.49,60.2 147.4,60.2 148.125,60.925 148.148,60.925
  Signal Layer 3 w0.2: J2.20@99.5,5.4 99.5,5.9 99.8,6.2 103,6.2 106.9,10.1 106.9,16.386 v1@114.1,23.586 ; v1(114.1,23.6) 113.87,23.83 113.87,35.997 125.2,47.327 ; v1(130.7,48.3) v1@130.7,54.3 ; v1(130.7,54.4) 130.7,54.417 131,54.717 131,60.183 130.7,60.483 v1(130.7,60.5)
  Bottom Layer w0.2: U20.1@120.3,9.399 120.537,9.636 120.537,10.182 120.679,10.324 121.921,10.324 122.063,10.182 122.063,9.611 U20.3@122.1,9.574 ; C36.1@122.8,13.749 R22.1@122.8,15.292
  Bottom Layer w0.3: v1@114.055,23.546 116.154,23.546 118.8,20.9 118.8,13.9 121.5,11.2 C35.1@123.068,11.2 ; L6.2@119.75,16.7 119.75,14.95 121.4,13.3 C36.1@123.084,13.3 ; R20.2@120.2,19.3 120.3,19.3 120.45,19.15 120.45,18.05 120.9,17.6 120.9,15.1 122.05,13.95 122.599,13.95 122.8,13.749 123.084,13.465 C36.1@123.084,13.3 ; U20.3@122.25,9.574 122.25,9.45 122.4,9.3 C981.1@123.7,9.3 123.7,10.15 123.553,10.297 123.553,10.715 C35.1@123.068,11.2 ; v1(125.341,47.6) 125.873,48.132 C11.1@128.8,48.132 130.451,48.132 130.619,48.3 v1(130.7,48.3) ; C35.1@123.068,11.2 123.084,11.216 C36.1@123.084,13.3
5Vp: C31.2 C63.1 C73.1 C76.1 L5.2 pad.1@71.175,62.85 R82.2 R251.2 R271.2 U1.5 U5.3 U5.4 U10.1 U10.3 U11.3 U11.8 | length 97.9
  Top Layer w0.2: C63.1@74.3,8.5 C63.1@74.5,8.7
  Top Layer w0.5: 72.7,8.5 U10.1@73.1,8.5
  Signal Layer 2 w0.4: v2(65.738,11.224) 65.738,16.038 69.8,20.1 69.8,33.6 74.323,38.123 74.323,54.977 69,60.3 69,64.1 69.6,64.7 70.6,64.7 71.175,64.125 pad.1@71.175,62.85
  Bottom Layer w0.2: R82.2@53.6,7 54.8,7 57.2,9.4 v2@57.2,10.5 ; v2@69.8,11.1 69.3,11.1 69.2,11 69.2,9.1 69.4,8.9 70.1,8.9 70.4,8.6 U1.5@70.4,7.875 ; L5.2@87.475,11.75 87.475,10.325 88.2,9.6 90.2,9.6 90.7,10.1 90.7,10.6 R271.2@90.8,10.7
  Bottom Layer w0.3: U11.8@73.455,10.55 73.455,9.462 73.817,9.1 76.1,9.1 76.1,7.774 ; v2@74.844,7.656 78.956,7.656 80.321,9.021 80.321,9.979 U11.3@79.9,10.4 ; R251.2@85.9,14.6 86,14.6 87.6,14.6 87.6,14.5 C73.1@87.226,14.126 ; v2(86.9,13.8) C73.1@87.226,14.126 ; L5.2@87.475,11.75 87.674,11.949 87.674,14.126 C73.1@87.226,14.126
  other v2: 74.825,7.675 57.175,10.475 69.838,11.124 71.177,63.239
5Vp: J21M.1 J22M.2 | length 21.7
  Signal Layer 1 w0.2: J21M.1@65.4,4.13 66.83,2.7 82.6,2.7 83.1,3.2 83.1,5.1 82.8,5.4 J22M.2@82.23,5.4 ; J22M.2@81.9,5.7 J22M.2@82.23,5.7
12Vp: Brd1.P2a Brd1.P2b C60.1 C66.1 C70.1 C71.1 J21A.20 pad.1@72.5,62.85 pad.1@83.25,52.45 pad.1@83.25,64.35 R89.2 U8.1 U9.3 U12.5 U12.6 | length 238.9
  Top Layer w0.2: J21A.20@103.3,31.17 J21A.20@103.37,31.1
  Top Layer w0.4: pad.1@72.5,63.5 72.5,64.4 74.4,66.3 v1(80.2,66.3)
  Top Layer w0.635: v2(34.1,65.7) 34.1,67.95 R89.2@34.3,68.15
  Signal Layer 3 w0.3: v2@40,26.41 40,22.3 41.8,20.5 49.6,20.5 62.5,7.6 65.7,7.6 66.9,6.4 85.875,6.4 v2(86.375,6.9)
  Signal Layer 4 w0.5: 34.7,66.3 v1(80.2,66.3)
  Signal Layer 4 w0.635: v2(34.1,65.7) 34.7,66.3
  Bottom Layer w0.2: C71.1@91.841,18.125 C71.1@91.966,18 ; J21A.20@103.3,31.17 J21A.20@103.37,31.1
  Bottom Layer w0.3: U8.1@39.85,29.425 39.85,29.15 40.3,28.7 40.3,26.8 40,26.5 v2(39.981,26.5) 40.783,26.5 42,27.717 42,33.75 C60.1@41.05,34.7 ; U12.5@89.525,16.025 U12.6@89.925,16.025 ; U12.6@90.025,15.85 90.025,16.309 C71.1@91.841,18.125
  Bottom Layer w0.4: v1@80.3,66.4 80.4,66.3 80.9,66.3 ; Brd1.P2b@83.26,65.601 83.26,66.3 80.9,66.3 ; Brd1.P2a@83.4,54.2 83.3,54.1 80.9,54.1 ; C70.1@89.75,20.8 C70.1@89.75,21.1 ; 90.145,22.825 87.6,25.37 87.6,35.8 80.9,42.5 80.9,54.1 ; C71.1@91.966,18 92.5,18 ; 80.9,54.1 80.9,64.081 80.9,66.3
  Bottom Layer w0.5: U9.3@32.85,65.83 34.23,65.83 v2(34.1,65.7) ; v2(86.375,6.9) 90.6,6.9 94.2,10.5 94.2,16.4 92.5,18.1 93.5,18.1 94.6,19.2 94.6,21.5 93.7,22.4 91.8,22.4 90.5,21.1 C70.1@89.8,21.1
  Bottom Layer w0.8: C70.1@89.8,21.2 89.8,22.48 92.22,24.9 101.8,24.9 104.5,27.6 104.5,30.3 103.7,31.1 J21A.20@103.37,31.1
  other v2: 72.498,63.239
12Vp_h: C67.2 C74.1 J21A.8 U11.11 U11.16 | length 44
  Top Layer w0.2: J21A.8@95.68,31.17 J21A.8@95.8,31.29
  Top Layer w0.4: v2(77.7,20.5) 79.2,22 v2(86.2,22)
  Signal Layer 2 w0.4: v2(86.2,22) 86.2,29.7 89.8,33.3 95.16,33.3 95.68,32.78 J21A.8@95.68,31.17
  Bottom Layer w0.2: C74.1@82.4,18.6 82.3,18.7 82.3,20.4 83.9,22 v2(86.2,22)
  Bottom Layer w0.5: U11.11@75.995,16.05 75.995,16.595 77,17.6 C67.2@77,18.9 77,20.3 77.2,20.5 v2(77.7,20.5) ; U11.16@82.345,16.05 C74.1@82.345,18.445
12VS: C17.1 C18.1 C30.2 C34.1 J2.2 J22A.2 U6.1 U15.2 | length 70.2
  Signal Layer 3 w0.2: v1(109.05,16.675) 109.05,17.85 ; 114.8,23.6 v1(114.8,30.7)
  Signal Layer 3 w1: J2.2@110.93,5.4 111.347,5.4 111.697,5.05 117.114,5.05 118.05,5.986 118.05,29.35 119.87,31.17 J22A.2@121.19,31.17
  Bottom Layer w0.2: v1(114.8,30.7) 115.27,31.17 120.07,31.17 ; J22A.2@121.19,31.17 120.07,31.17 ; C34.1@123.25,22.42 120.78,22.42 119.9,23.3 119.9,31 120.07,31.17
  Bottom Layer w0.3: v1@109.25,16.775 U6.1@110.1,16.775 ; U15.2@123.25,19.34 C34.1@123.25,22.42
  Bottom Layer w0.4: v1(109.05,16.675) C18.1@109.05,15.575 109.15,15.575 109.25,15.475 109.25,15.159 109.484,14.925 110.825,14.925 111.85,13.9 C17.1@111.85,13.875
12VSB: J4.5 J22A.3 J22A.4 J22A.6 | length 47.3
  Top Layer w1: J22A.3@122.46,29.9 J22A.4@122.46,31.17 J22A.6@123.73,31.17
  Signal Layer 2 w0.8: 122.46,29.14 J22A.3@122.46,29.9 J22A.4@122.46,31.17 J22A.6@123.57,31.17
  Signal Layer 2 w1: 122.46,29.14 122.46,28.84 125.1,26.2 125.1,23.7 129.8,19 152.2,19 J4.5@154.8,16.4
  Bottom Layer w0.8: J22A.3@122.46,30.04 J22A.4@122.46,31.17 J22A.6@123.73,31.17
54Vout: Q1.5-6-7-8 Q2.5-6-7-8 Q3.5-6-7-8 Q6.5-6-7-8 R11.2 R19.1 U3.6 | length 33.5
  Signal Layer 2 w0.3: v1(142.7,38.6) 143.836,38.6 146.736,35.7 v1(149,35.7)
  Bottom Layer w0.2: R19.1@151.4,18.8 151.4,20.6 157.7,26.9 157.7,36.1 v9(155.9,37.9)
  Bottom Layer w0.3: R11.2@140.1,37.2 140.2,37.3 140.2,37.85 140.9,38.55 U3.6@141.1,38.55 141.125,38.575 142.675,38.575 v1(142.7,38.6)
  other v1: 155.9,36 156.763,36.236 154.9,36.3 154.3,37 146.7,37.8 148.1,37.8 150,37.8 151.4,37.8 154,37.9 154.3,38.9 145.9,39.2 147.3,39.2 149.2,39.2 150.6,39.2 155,39.5 156.9,39.5 155.9,39.8
54Vout-1: C4.1 C4A.1 C5.1 C6.1 C20.1 D3.1 pad.1@141.9,35.7 Q1.1-2-3-4 Q2.1-2-3-4 Q3.1-2-3-4 Q6.1-2-3-4 U3.4 | length 23.9
  Signal Layer 2 w0.3: 140.414,37.6 140.714,37.9 142.551,37.9 143.9,37.9 v1(148.9,32.9)
  Bottom Layer w0.3: D3.1@133.01,36.7 D3.1@133.7,37.39 ; U3.4@141.1,40.45 142.65,40.45 C20.1@142.9,40.7 143.05,40.7 143.475,40.275 143.475,40.124 143.5,40.099 143.5,35.5 144.3,34.7 147.2,34.7 ; 147.2,33.925 147.2,34.7
  Bottom Layer w0.5: U3.4@141.069,40.481 U3.4@141.1,40.45
+BRDG_N: pad.1@26.95,60.55 U9.7 | length 25.1
  Signal Layer 4 w0.3: v2@26.4,67.1 19.7,67.1 18.3,65.7 18.3,59.8 19.177,58.923 25.823,58.923 25.827,58.923 26.327,59.423 26.327,59.427 v2(26.95,60.05)
  Bottom Layer w0.3: v2@26.4,67.1 U9.7@27.4,67.1
  other v2: 26.425,67.075
+BRDG_P: pad.1@29.675,60.55 U9.5 | length 13.1
  Top Layer w0.3: v2@28.825,64.55 v2(28.825,64.575)
  Signal Layer 1 w0.2: v2(28.825,64.575) 31.625,64.575 32.6,63.6 32.6,59.7 32.1,59.2 30.3,59.2 29.7,59.8 pad.1@29.7,60
  Bottom Layer w0.3: U9.5@27.325,64.57 v2@28.795,64.57
  other v2: 29.65,60.05
AC_CUR_SENSE: J21M.13 U7.7 | length 10.2
  Top Layer w0.3: U7.7@51.525,6.335 52.165,6.335 53.1,5.4 53.1,2.5 56.3,2.5 J21M.13@57.8,4
ACL_SENSE: J21M.19 R62.1 | length 30.8
  Signal Layer 2 w0.2: J21M.19@54.17,4.13 54.17,3.83 55.8,2.2 66.7,2.2 67.6,3.1 67.6,13.7 69.1,15.2 69.1,15.9 v2@68.4,16.6
  Signal Layer 2 w0.3: J21M.19@54.047,4.053 J21M.19@54.07,4.03
  Bottom Layer w0.5: v2@68.35,16.65 R62.1@68.35,18.2
  other v2: 68.338,16.524
ACN_SENSE: J21M.9 R87.1 | length 21.9
  Signal Layer 2 w0.2: J21M.9@60.52,4.13 60.52,3.88 61.8,2.6 66.4,2.6 67.1,3.3 67.1,14.2 v2@68.2,15.3
  Signal Layer 2 w0.3: v2@68.2,15.287 v2@68.2,15.3 ; v2@68.207,15.293 v2(68.238,15.324)
  Bottom Layer w0.5: v2@68.2,15.3 68.25,15.25 R87.1@68.25,13.6
ADDR_A0: J2.3 J4.2 | length 63.9
  Top Layer w0.2: J2.3@109.66,4.13 109.66,3.24 111.5,1.4 143.8,1.4 153.8,11.4 157.4,11.4 158,12 158,19.4 156.9,20.5 J4.2@156.351,20.5
ADDR_A1: J1.14 J4.4 | length 27.6
  Signal Layer 1 w0.2: J1.14@135.41,5.4 135.544,5.534 135.544,5.844 137,7.3 146.305,7.3 154.511,15.506 154.688,15.506 ; 154.689,15.506 154.699,15.506 ccw(c154.8,16.4) 155.694,16.501 155.694,16.511 155.694,16.594 156.8,17.7 J4.4@156.8,18.4
AGND: C1.1 C8.1 C9.2 C10.2 C13.2 C17.2 C18.2 C19.2 C23.2 C24.2 C25.1 C27.2 C28.2 J2.14 J2.16 J2.18 J2.19 Q10.1 Q10.4 R9.1 R16.1 U2.2 U6.10 U6.11@112.325,17.775 U31.3 U31.4 U31.7 | length 107.3
  Signal Layer 3 w0.5: J2.19@99.5,4.13 99.423,4.207 98.693,4.207 98.433,4.467 98.433,6.133 99.25,6.95 102.857,6.95 106.15,10.243 106.15,16.343 113.3,23.493 113.3,36.134 121.8,44.634 v1(121.8,45.3) 124.7,48.2 v1(124.7,56.7)
  Signal Layer 4 w0.3: v4(113.125,16.575) 113.125,13.2 v1(114.15,12.175)
  Bottom Layer w0.2: U6.11@113.25,18.975 113.35,19.075 C23.2@113.35,19.975 ; C8.1@119.6,42.7 119.6,42.725 121,44.125 121.125,44.125 C13.2@121.5,44.5 ; R9.1@121.5,45.9 121.5,45.6 v1(121.8,45.3) 121.8,44.8 C13.2@121.5,44.5 ; U2.2@122.2,42.875 122.2,43.825 121.525,44.5 C13.2@121.5,44.5
  Bottom Layer w0.3: J2.14@103.31,5.4 103.341,5.431 103.341,6.041 104.4,7.1 C9.2@105.5,7.1 ; C18.2@110.25,15.575 110.35,15.575 111.15,16.375 111.5,16.375 111.65,16.525 111.65,16.575 111.75,16.475 111.75,15.575 C17.2@111.85,15.475 ; C24.2@111.35,20.275 111.75,19.875 U6.11@111.75,18.775 ; C27.2@111.96,11.27 113.193,11.27 ; C25.1@112.62,10.16 112.695,10.16 112.92,10.385 112.92,10.46 113.193,10.733 113.193,11.27 ; Q10.1@113.193,12.018 113.193,11.27 ; Q10.1@113.2,12.025 114.1,12.025 114.15,12.075 v1(114.15,12.175) 114.207,12.232 114.207,12.717 114.756,13.265 115.04,13.265 Q10.4@115.1,13.325 115.113,13.313 117.187,13.313 C19.2@117.2,13.3 ; R16.1@113.25,15.675 U6.11@113.25,16.675 ; U6.11@113.25,16.775 U6.10@114.55,16.775 U6.10@114.675,16.775 ; U31.4@121.7,60.9 121.3,60.5 121.3,57.6 121.835,57.065 U31.7@122.475,57.065 124.165,57.065 C1.1@124.7,57.6 ; U31.3@122.475,62.145 122.475,60.925 U31.4@122.5,60.9 ; C10.2@124.7,55.9 v1(124.7,56.7) C1.1@124.7,57.5
  other v4: 111.525,16.575 112.325,16.575 111.525,18.975 112.325,18.975 113.125,18.975
  other v6: 111.525,17.375 112.325,17.375 113.125,17.375 111.525,18.175 112.325,18.175 113.125,18.175
BB_BYPAS: D8.1 R58.2 U11.10 | length 53.1
  Bottom Layer w0.2: D8.1@54.2,44.637 54.063,44.5 53,44.5 52.7,44.2 52.7,40.9 53.095,40.505 55.579,40.505 ; D8.1@54.5,44.6 55.8,44.6 R58.2@56.2,45 ; v2@56,40.7 56.75,39.95 72.67,39.95 76.8,35.82 76.8,21.3 74.938,19.438 v2(74.938,17.124)
  Bottom Layer w0.5: U11.10@74.7,16.2 74.825,16.325 v2@74.825,17.025
  other v2: 55.825,40.675
BB_CS: J22M.9
BB_ONOFF: C69.1 J22M.3 U11.2 | length 26.3
  Top Layer w0.3: J22M.3@81.04,3.93 82.07,2.9 82.8,2.9 83.5,3.6 83.5,9.7 C69.1@82.2,11
  Bottom Layer w0.3: J22M.3@80.8,3.8 80.8,3.6 81.4,3 82.9,3 83.6,3.7 83.6,11.7 81.2,11.7 81.075,11.575 U11.2@81.075,10.55
BBDRV: Q7.1 R77.2 R90.1 R91.2 | length 20
  Bottom Layer w0.3: R77.2@36.4,31.2 36.2,31 35.6,31 35.6,27.97 35.67,27.9 R91.2@36.4,27.9 R90.1@37.9,27.9 ; R90.1@37.9,27.5 R90.1@37.9,28 ; R90.1@37.9,27.8 R90.1@38.1,27.8 ; 37.948,27.352 40.1,25.2 48.6,25.2 48.8,25.4 Q7.1@48.8,26.6
BBFET: J22M.5 R88.1 | length 56.9
  Signal Layer 3 w0.3: v2(41,27.5) 40.1,27.5 39.3,26.7 39.3,22.1 41.5,19.9 49.5,19.9 62.3,7.1 65.3,7.1 69.2,3.2 78.76,3.2 J22M.5@79.69,4.13
  Bottom Layer w0.3: v2(41,27.5) 41.25,27.75 R88.1@41.25,29.1
CR-BUS: J1.12 J4.8 | length 23.8
  Signal Layer 1 w0.2: J1.12@136.68,5.4 136.814,5.534 137.094,5.534 138.46,6.9 146.4,6.9 152.9,13.4 155.3,13.4 156.3,14.4 J4.8@156.8,14.4
DRV_Relay: D10.1 R64.1 U11.15 | length 31.6
  Bottom Layer w0.2: R64.1@72.9,41 73.1,40.8 75.1,40.8 77.3,38.6 77.3,23.6 81.138,19.762 81.138,17.224
  Bottom Layer w0.3: D10.1@70.7,40.862 R64.1@72.9,40.862
  Bottom Layer w0.5: U11.15@81.075,16.05 81.075,17.1
GaN1_FLT: Brd1.P5a pad.1@86.275,49.275 U14.6 | length 21.2
  Signal Layer 2 w0.2: pad.1@86.2,48.8 86.2,46.5 89.3,43.4 93.9,43.4 94.2,43.1 94.2,40.5 97.826,36.874 98.126,36.874 v1(98.2,36.8)
  Bottom Layer w0.2: v1(98.2,36.8) U14.6@99.6,36.8
GaN2_FLT: Brd1.P5b pad.1@86.275,61.375 U14.1 | length 35.3
  Signal Layer 2 w0.2: pad.1@86.4,60.9 86.3,60.8 86.3,56.5 89.1,53.7 89.1,45.8 90.3,44.6 94.9,44.6 97.3,42.2 97.3,38.1 97.7,37.7 v1(98.2,37.7)
  Bottom Layer w0.2: v1(98.2,37.7) 101.4,37.7 101.7,37.4 U14.1@101.7,36.9
GaN_Fault: J22M.19 pad.1@72.5,60.575 | length 61.9
  Signal Layer 2 w0.3: J22M.19@70.8,4.13 69.57,4.13 68.3,5.4 68.3,11.2 71.1,14 71.1,33.2 75.4,37.5 75.4,55.7 72.475,58.625 v2(72.475,60.1)
GaN_TMP: J22M.17
HFFET_HS: pad.1@73.775,62.85 U1.4 | length 69.4
  Signal Layer 2 w0.3: v2(71.1,7.1) 72.7,8.7 72.7,31.9 79.65,38.85 79.65,64.65 79.6,64.7 79.45,64.85 79,65.3 74.9,65.3 73.768,64.168 v2(73.768,63.239)
  Bottom Layer w0.3: U1.4@71.05,7.875 71.05,7.15 v2(71.1,7.1)
HFFET_LS: pad.1@75.05,62.85 U1.6 | length 67.2
  Signal Layer 2 w0.3: v2(69.8,7.1) 72.1,9.4 72.1,32.1 79.2,39.2 79.2,64.3 78.8,64.7 75.8,64.7 75.038,63.938 v2(75.038,63.239)
  Bottom Layer w0.3: v2(69.8,7.1) U1.6@69.8,7.825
